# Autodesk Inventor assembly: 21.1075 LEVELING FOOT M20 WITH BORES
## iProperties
Created: 2007-03
Part Number: 21.1075 LEVELING FOOT M20 WITH BORES
Document SubType Name: Assembly
Designer: Andy Moles
Author: Andy Moles
